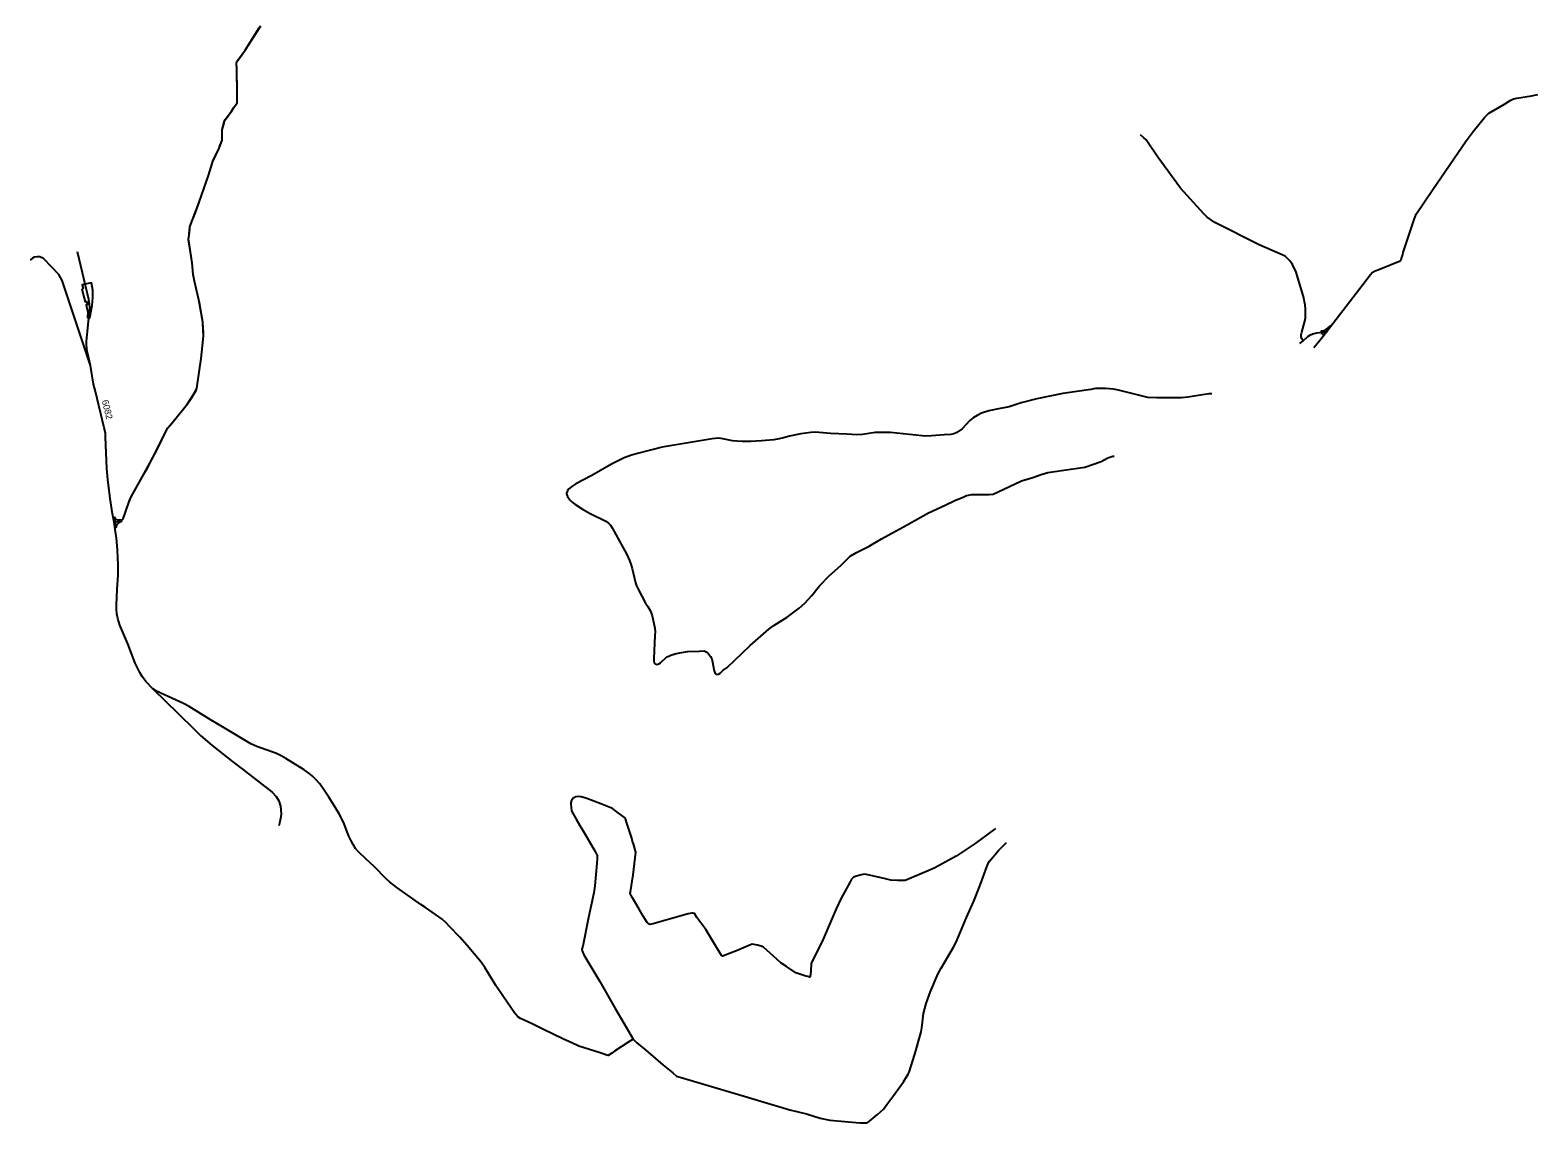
# Model space of a CAD drawing. Extents: x -444937 to -436355, y -1135022 to -1129798.
# Drawn here: x -444937 to -442668, y -1134559 to -1132915 of the extents above; entities that cross this region are included whole.
import ezdxf

# ---------------------------------------------------------------- set-up
doc = ezdxf.new("R2010")
doc.units = 0
for name, color, linetype in [('Vrstva 12', 7, 'Continuous'), ('Vrstva 29', 7, 'Continuous'), ('Vrstva 75', 7, 'Continuous'), ('Vrstva 8', 7, 'Continuous')]:
    doc.layers.add(name, color=color, linetype=linetype)

msp = doc.modelspace()

# ---------------------------------------------------------------- linework, layer by layer
at = {"layer": 'Vrstva 12'}
for points in [[(-444810.7, -1133655.8), (-444804, -1133654.8), (-444800.5, -1133653.5), (-444797.4, -1133650.5), (-444788, -1133624.4), (-444785.2, -1133617.7), (-444762.9, -1133578.2), (-444754.2, -1133561.6), (-444744.3, -1133542.3), (-444733.8, -1133521.3), (-444729.9, -1133513.9), (-444725.7, -1133508.6), (-444706.5, -1133485), (-444700.6, -1133477.9), (-444694.1, -1133467.9), (-444689.6, -1133460.8), (-444688.1, -1133458.5), (-444686.5, -1133453.9), (-444679.9, -1133409.3), (-444676.7, -1133381.1), (-444676.5, -1133375.2), (-444676.2, -1133370.9), (-444677.2, -1133354.9), (-444683.2, -1133321.2), (-444689.7, -1133293.2), (-444691.9, -1133283), (-444693.6, -1133265.4), (-444697.8, -1133236.9), (-444698.8, -1133230.7), (-444697.9, -1133223), (-444697.5, -1133216.2), (-444696.9, -1133211.3), (-444693.8, -1133203.1), (-444688.5, -1133189.8), (-444682.9, -1133174.4), (-444668.8, -1133134.2), (-444664.8, -1133121.3), (-444662.2, -1133112.9), (-444652.8, -1133093.2), (-444648, -1133081.2), (-444648, -1133075.9), (-444648.2, -1133065.2), (-444644.5, -1133052.1), (-444643.3, -1133049.9), (-444633.9, -1133036.9), (-444630.5, -1133031.8), (-444625.5, -1133024.8), (-444625.5, -1132998.6), (-444626, -1132982.6), (-444626.4, -1132973.1), (-444626.8, -1132966.9), (-444626.8, -1132965.1), (-444626.4, -1132963), (-444613.4, -1132945.4), (-444590.2, -1132908.7)], [(-443021.3, -1133382.7), (-443023.5, -1133379.8), (-443024.2, -1133376.6), (-443024.1, -1133373.8), (-443023.2, -1133370), (-443018.6, -1133353.5), (-443017.9, -1133348.3), (-443017.8, -1133342.7), (-443017.8, -1133335.4), (-443018.4, -1133328.9), (-443019.3, -1133324.4), (-443020.5, -1133318.4), (-443031.9, -1133279.7), (-443037.1, -1133267.8), (-443041.3, -1133262.4), (-443044.2, -1133259.5), (-443048.4, -1133255.7), (-443087.3, -1133238.2), (-443154.2, -1133204.7), (-443160.9, -1133200.1), (-443165.8, -1133196.8), (-443171, -1133191.6), (-443205.9, -1133153.1), (-443239.9, -1133106.7), (-443254.3, -1133085), (-443257.5, -1133080.7), (-443261.2, -1133077.3), (-443266, -1133073.1)], [(-444029.7, -1134433.4), (-444036.1, -1134437.5), (-444057.5, -1134451.4), (-444061.9, -1134454.6), (-444067.2, -1134458.1), (-444069.4, -1134457.7), (-444070.7, -1134457.1), (-444079.3, -1134454.1), (-444111.2, -1134443.9), (-444122.2, -1134438.9), (-444134.5, -1134433.4), (-444165.4, -1134418.5), (-444181.8, -1134410.6), (-444199.3, -1134402.5), (-444203.3, -1134400.1), (-444208.1, -1134393.8), (-444224.9, -1134369.7), (-444236.5, -1134352.7), (-444252.8, -1134325.6), (-444258.3, -1134317.7), (-444279.7, -1134292.7), (-444290.6, -1134279.9), (-444306, -1134263.8), (-444311.2, -1134258.5), (-444316.9, -1134253.2), (-444342.3, -1134235.7), (-444349.4, -1134230.9), (-444385.3, -1134205.4), (-444396.4, -1134196.8), (-444401.3, -1134192.1), (-444419.3, -1134173.8), (-444432.2, -1134162.1), (-444443.1, -1134151.6), (-444447.4, -1134146.5), (-444450.9, -1134140.9), (-444454.5, -1134134.2), (-444457.5, -1134127.9), (-444461.1, -1134119.1), (-444464.8, -1134109.5), (-444467.8, -1134102.9), (-444472.3, -1134094.3), (-444479, -1134082.8), (-444487.5, -1134069.6), (-444493.5, -1134060.2), (-444501.4, -1134049.5), (-444508.3, -1134041.9), (-444512.9, -1134037.4), (-444517.8, -1134033.5), (-444524.9, -1134028.5), (-444552.5, -1134011.3), (-444559.6, -1134007.3), (-444566.4, -1134004), (-444596.2, -1133993.1), (-444605.2, -1133989.1), (-444612.7, -1133984.7), (-444647.7, -1133963.4), (-444664.8, -1133953.5), (-444697.7, -1133932.8), (-444706.4, -1133928.7), (-444717.5, -1133923.6), (-444747.3, -1133909.8), (-444752.5, -1133906.4), (-444763, -1133895.2), (-444768.5, -1133888), (-444772.2, -1133882), (-444779.1, -1133867.6), (-444790.3, -1133838.9), (-444802.2, -1133810.5), (-444805.5, -1133800.4), (-444806.7, -1133793.6), (-444807.1, -1133786.4), (-444807.1, -1133780), (-444806.1, -1133757.2), (-444804.8, -1133734.8), (-444804.8, -1133720), (-444805.1, -1133709.2), (-444805.6, -1133697.4), (-444807.3, -1133679.6), (-444809.1, -1133666.7), (-444810.7, -1133655.8), (-444813.3, -1133643), (-444816.6, -1133619.9), (-444820.5, -1133591.7), (-444821.8, -1133575.2), (-444823.9, -1133527.7), (-444824, -1133521.2), (-444825.6, -1133513.8), (-444839.1, -1133459.1), (-444841.7, -1133448.2), (-444846.6, -1133419.8), (-444851.1, -1133400.2), (-444851.9, -1133394.3), (-444852.4, -1133388.4), (-444852.2, -1133384.1), (-444847.6, -1133333.3), (-444847.7, -1133327.2), (-444848.7, -1133320.5), (-444865.8, -1133249)], [(-444846.6, -1133419.8), (-444888.9, -1133292.1), (-444894.2, -1133283), (-444904.8, -1133271.9), (-444917.3, -1133259.2), (-444922.8, -1133256.5), (-444926.9, -1133256.5), (-444931, -1133257.2), (-444933.6, -1133258.7), (-444937.2, -1133261.6)], [(-443026.1, -1133386.9), (-443021.3, -1133382.7), (-443014.2, -1133376.5), (-443010.3, -1133373.8), (-443006.9, -1133372.4), (-443000.5, -1133370.7), (-442984.7, -1133368.7)], [(-443836.6, -1133533.2), (-443852.8, -1133534.1), (-443865.6, -1133534.4), (-443873.8, -1133534), (-443880.1, -1133533.4), (-443894.7, -1133530.3), (-443900.7, -1133529.4), (-443906, -1133529.7), (-443910.9, -1133530.2), (-443986.1, -1133542.8), (-444023, -1133552.5), (-444033.6, -1133555.6), (-444043.1, -1133559.1), (-444062.1, -1133568.4), (-444091.9, -1133585.3), (-444115.8, -1133598.1), (-444122.2, -1133601.8), (-444126.7, -1133605.4), (-444128.5, -1133608.4), (-444129.8, -1133612.3), (-444129.7, -1133614.7), (-444128.6, -1133617.3), (-444125, -1133622.1), (-444121.5, -1133625.8), (-444117.7, -1133628.7), (-444106.1, -1133636.3), (-444094.4, -1133642.9), (-444070.8, -1133654.2), (-444066.7, -1133657.1), (-444063.8, -1133660.4), (-444061.3, -1133664.1), (-444039.2, -1133704.5), (-444035.2, -1133713.2), (-444033, -1133718.7), (-444031.1, -1133725.3), (-444026.3, -1133747.2), (-444024.7, -1133751.6), (-444022.2, -1133756.3), (-444010.9, -1133777.6), (-444007.6, -1133782.8), (-444004.1, -1133788.4), (-444002.5, -1133792.3), (-444000.9, -1133796.8), (-443997, -1133815.4), (-443996.7, -1133820.5), (-443996.9, -1133826.1), (-443998.8, -1133860.7), (-443998.7, -1133864.5), (-443998.1, -1133867.1), (-443996.3, -1133869), (-443993.5, -1133869.7), (-443991.1, -1133869), (-443988.7, -1133867.1), (-443978.8, -1133858.3), (-443976.2, -1133857.1), (-443973, -1133855.6), (-443966.4, -1133854)], [(-444752.5, -1133906.4), (-444714.3, -1133943.6), (-444690.6, -1133967.1), (-444680.3, -1133977.2), (-444663.5, -1133991.8), (-444632.4, -1134016.4), (-444617.4, -1134027.5), (-444572.8, -1134062), (-444567, -1134068.4), (-444562.9, -1134075.2), (-444560.5, -1134083), (-444559.5, -1134094.5), (-444559.8, -1134098.9), (-444561.2, -1134106.4), (-444563.2, -1134112.5)], [(-443484.1, -1134116.4), (-443514.7, -1134139), (-443543.5, -1134158.2), (-443559.3, -1134166.8), (-443575.7, -1134176), (-443584.9, -1134179.9), (-443610.7, -1134190.8), (-443620.5, -1134194.8), (-443625.4, -1134194.8), (-443631.8, -1134194.7), (-443641.6, -1134194.3), (-443650.1, -1134192.4), (-443673.9, -1134186.9), (-443681.3, -1134185.5), (-443688.6, -1134187), (-443698.2, -1134189.6), (-443700.8, -1134193), (-443703.6, -1134197.9), (-443716.7, -1134221.2), (-443724.1, -1134237.5), (-443745.2, -1134286.4), (-443758.8, -1134313), (-443761.6, -1134319.6), (-443762.5, -1134331.1), (-443763.4, -1134339.6), (-443764.2, -1134340.2), (-443765.2, -1134340), (-443767, -1134339.5), (-443769.9, -1134338.8), (-443780.2, -1134335.3), (-443784.7, -1134333.7), (-443798.9, -1134324.4), (-443807.6, -1134318.7), (-443818.6, -1134308.9), (-443833.3, -1134295.2), (-443836.8, -1134293.6), (-443842.3, -1134292.1), (-443850.5, -1134290.6), (-443852.9, -1134291.6), (-443874.3, -1134300.5), (-443888.5, -1134306.4), (-443894.5, -1134308.7), (-443895.8, -1134308.5), (-443896.7, -1134307.7), (-443898.2, -1134305.2), (-443908.3, -1134288.4), (-443920.4, -1134268.7), (-443933.6, -1134250.4), (-443937.5, -1134244.5), (-443939.2, -1134243.8), (-443941.5, -1134243.8), (-443947, -1134245.1), (-443973.5, -1134252.5), (-443990.8, -1134257.4), (-443999.4, -1134260.1), (-444004.4, -1134261.1), (-444006.8, -1134260), (-444008.8, -1134257.8), (-444014.4, -1134248.4), (-444020.6, -1134238.2), (-444030.5, -1134221), (-444032.6, -1134217.5), (-444034, -1134214.4), (-444033.9, -1134212), (-444029.5, -1134186.5), (-444025.4, -1134152.4), (-444029.4, -1134139.8), (-444030.5, -1134136.4), (-444031.7, -1134131.3), (-444038.7, -1134109.9), (-444041.4, -1134102.2), (-444042.9, -1134100.1), (-444054.1, -1134091.3), (-444060.9, -1134086.3), (-444078.2, -1134079.3), (-444099.3, -1134071.7), (-444107.9, -1134068.9), (-444112.2, -1134068.2), (-444116, -1134069), (-444119.9, -1134071.1), (-444122.6, -1134074.3), (-444123.3, -1134077.4), (-444123.6, -1134080.2), (-444122.3, -1134089.9), (-444115.6, -1134102.4), (-444109.9, -1134112), (-444103, -1134123.5), (-444086.9, -1134151.2), (-444083.6, -1134157.3), (-444083.7, -1134161.7), (-444084.5, -1134168.8), (-444087.3, -1134203.1), (-444089, -1134213.2), (-444096.9, -1134250.7), (-444105.5, -1134293.7), (-444106.7, -1134298), (-444106.6, -1134300.6), (-444103.8, -1134306.6), (-444079.9, -1134346.7), (-444057.3, -1134386.2), (-444043.6, -1134409.3), (-444029.7, -1134433.4), (-444024.2, -1134439.2), (-444010.8, -1134450.3), (-443996.1, -1134462.6), (-443984.9, -1134472), (-443970.2, -1134484.1), (-443964.2, -1134489.1), (-443957.2, -1134491.3)], [(-443957.2, -1134491.3), (-443930.4, -1134499.2), (-443862.4, -1134519.2), (-443837.3, -1134527), (-443793.8, -1134539.9), (-443768.7, -1134546.1), (-443748, -1134552.3), (-443733.9, -1134555.2), (-443688.5, -1134559.2), (-443682.3, -1134559.4), (-443677.6, -1134559.4), (-443673.9, -1134556.8), (-443662.1, -1134546.8), (-443653.1, -1134538.9), (-443648.1, -1134531.9), (-443638.9, -1134519.8), (-443626.6, -1134503.3), (-443622.9, -1134497.7), (-443615.9, -1134486), (-443614.4, -1134483), (-443605.7, -1134456.1), (-443596.4, -1134422.7), (-443595.2, -1134416.4), (-443592.5, -1134394.8), (-443588.9, -1134380), (-443582.3, -1134361.9), (-443570.7, -1134335), (-443566.3, -1134326.5), (-443547.4, -1134295.2), (-443543.4, -1134287.6), (-443527.8, -1134250.5), (-443517.1, -1134225.7), (-443508.2, -1134204.4), (-443495.7, -1134170.2), (-443493.2, -1134165.6), (-443479.9, -1134149.8), (-443467.6, -1134137.6)]]:
    msp.add_lwpolyline(points, dxfattribs=at)
for points in [[(-442994.2, -1133371.5), (-442992.7, -1133371.6), (-442991.5, -1133372.1), (-442991, -1133372.8), (-442991.4, -1133375), (-442985.2, -1133366.6), (-442980.4, -1133360.2), (-442984.5, -1133363.9), (-442987.5, -1133366), (-442990.3, -1133367.6), (-442994.4, -1133368.5)], [(-444811, -1133647.8), (-444809.5, -1133650.1), (-444808.1, -1133651.4), (-444806, -1133652.2), (-444804.1, -1133652.3), (-444801, -1133652), (-444799.6, -1133654.6), (-444803.9, -1133656.8), (-444806.2, -1133659), (-444807.2, -1133660.7), (-444808.2, -1133663.7), (-444809.5, -1133655.4)]]:
    msp.add_lwpolyline(points, close=True, dxfattribs=at)
at = {"layer": 'Vrstva 29'}
msp.add_lwpolyline([(-444859.5, -1133304.6), (-444857.2, -1133313.2), (-444854.4, -1133324.1), (-444852.2, -1133323.5), (-444850.8, -1133328.2), (-444853, -1133328.8), (-444851.8, -1133333.5), (-444850.7, -1133337.8), (-444850.5, -1133339.9), (-444850.7, -1133348), (-444847.2, -1133348.3), (-444844.1, -1133329.9), (-444842.7, -1133317.6), (-444842.7, -1133311.8), (-444842.7, -1133306.7), (-444845.1, -1133295.5), (-444852.5, -1133297.1), (-444859, -1133298.4), (-444857.5, -1133304.1)], close=True, dxfattribs=at)
at = {"layer": 'Vrstva 75'}
for points in [[(-444810.7, -1133655.8), (-444804, -1133654.8), (-444800.5, -1133653.5), (-444797.4, -1133650.5), (-444788.5, -1133625.9), (-444786, -1133619.8), (-444785, -1133617.6), (-444763.9, -1133579.9), (-444761.6, -1133575.9), (-444752.5, -1133558.3), (-444733.8, -1133521.3), (-444729.9, -1133513.9), (-444726.6, -1133509.7), (-444708.6, -1133487.7), (-444700.6, -1133477.5), (-444694.8, -1133468.9), (-444691.4, -1133463.5), (-444688.3, -1133458.5), (-444686.5, -1133453.9), (-444679.9, -1133409.3), (-444676.7, -1133381.1), (-444676.5, -1133375.2), (-444676.8, -1133367.2), (-444677.2, -1133354.9), (-444682.3, -1133325.5), (-444689.7, -1133293.2), (-444691.9, -1133283), (-444693.6, -1133265.4), (-444697.5, -1133238.8), (-444699.1, -1133229.4), (-444698.1, -1133223.9), (-444697.1, -1133215.4), (-444696.9, -1133211.3), (-444688.7, -1133190.2), (-444682.7, -1133174), (-444668.8, -1133134.2), (-444663.2, -1133115.9), (-444662.2, -1133112.7), (-444652.8, -1133093.2), (-444651.2, -1133088.2), (-444649.3, -1133084.2), (-444648, -1133081.2), (-444648.2, -1133065.2), (-444645.9, -1133056.8), (-444644.5, -1133052.1), (-444643.6, -1133050.1), (-444634.4, -1133037.3), (-444630.5, -1133031.9), (-444627.8, -1133027.9), (-444625.5, -1133024.8), (-444625.5, -1133001.4), (-444626, -1132985.2), (-444626.4, -1132973.1), (-444626.9, -1132965.7), (-444626.4, -1132962.7), (-444613.4, -1132945.4), (-444592.4, -1132911.9)], [(-444846.6, -1133419.8), (-444888.9, -1133292.1), (-444894.2, -1133283), (-444904.8, -1133271.9), (-444917.3, -1133259.2), (-444922.8, -1133256.5), (-444926.9, -1133256.5), (-444931, -1133257.2), (-444933.6, -1133258.7), (-444937.2, -1133261.6)], [(-444810.7, -1133655.8), (-444813.3, -1133643), (-444816.6, -1133619.9), (-444820.5, -1133591.7), (-444821.8, -1133575.2), (-444823.9, -1133527.7), (-444824, -1133521.2), (-444825.6, -1133513.8), (-444839.1, -1133459.1), (-444841.7, -1133448.2), (-444846.6, -1133419.8)]]:
    msp.add_lwpolyline(points, dxfattribs=at)
at = {"layer": 'Vrstva 8'}
for points in [[(-443005, -1133392.9), (-442997.9, -1133384.1), (-442991.5, -1133376.6), (-442966.5, -1133343.6), (-442936.6, -1133304.4), (-442920, -1133283.1), (-442917.5, -1133280.2), (-442913.9, -1133278.1), (-442909, -1133276.1), (-442905, -1133274.5), (-442875.4, -1133262.5), (-442873.6, -1133260.7), (-442871.5, -1133253), (-442870.6, -1133250.1), (-442861.6, -1133223.1), (-442854.2, -1133200.1), (-442851.4, -1133192.5), (-442826, -1133155.3), (-442776, -1133082.1), (-442765.2, -1133068), (-442748.2, -1133046.7), (-442744.3, -1133042.7), (-442740.9, -1133039.9), (-442718.4, -1133026.6), (-442709.6, -1133021.4), (-442704.8, -1133018.9), (-442699.5, -1133017.8), (-442677.6, -1133014.1), (-442668, -1133012.4)], [(-443158.7, -1133462.4), (-443163, -1133462.4), (-443194.6, -1133467.5), (-443204.6, -1133468.4), (-443226.3, -1133468.5), (-443241.7, -1133468.4), (-443255.2, -1133468), (-443299.1, -1133457.3), (-443306.5, -1133455.6), (-443318.9, -1133454.6), (-443333.9, -1133454.8), (-443340.9, -1133456.1), (-443382.8, -1133462.2), (-443421.9, -1133470.3), (-443445.5, -1133476.3), (-443463.9, -1133482.2), (-443479.7, -1133485.2), (-443494.3, -1133488), (-443505.2, -1133491.7), (-443512, -1133495.1), (-443517.9, -1133498.8), (-443522.8, -1133502.5), (-443534.7, -1133515.1), (-443542.3, -1133520.7), (-443546.8, -1133522.9), (-443551.5, -1133524), (-443561.5, -1133524.5), (-443580.6, -1133525.8), (-443589, -1133526.2), (-443594.7, -1133525.8), (-443642.6, -1133520.7), (-443653, -1133520.9), (-443665.4, -1133520.9), (-443684.5, -1133523.7), (-443693.2, -1133524.3), (-443708.2, -1133523.3), (-443732.9, -1133522.3), (-443738.1, -1133521.9), (-443755.2, -1133520.4), (-443762.1, -1133520.8), (-443777.2, -1133522.6), (-443794.2, -1133526.3), (-443803.5, -1133529), (-443809.7, -1133530.3), (-443818, -1133531.6), (-443836.6, -1133533.2)], [(-443966.8, -1133853.9), (-443959.4, -1133852.2), (-443947.9, -1133850.4), (-443930.2, -1133849.6), (-443922.8, -1133849.4), (-443917.7, -1133851.9), (-443913.3, -1133858), (-443911.1, -1133861.2), (-443907.7, -1133879.2), (-443906.3, -1133883.2), (-443904.2, -1133884.8), (-443901.1, -1133884.5), (-443898.8, -1133882.7), (-443894.8, -1133879), (-443888.3, -1133874.2), (-443853.4, -1133841.2), (-443825.7, -1133816.8), (-443817.9, -1133811.2), (-443797.8, -1133798.7), (-443779.8, -1133785.1), (-443771.1, -1133777.7), (-443760.9, -1133765.9), (-443749.4, -1133751.6), (-443734.5, -1133736.6), (-443717.3, -1133721.1), (-443703, -1133707.1), (-443693.6, -1133701.4), (-443674.7, -1133691.6), (-443656, -1133681), (-443618.2, -1133660.1), (-443585, -1133641.8), (-443560.2, -1133630.3), (-443544.7, -1133622.8), (-443533.2, -1133618), (-443528, -1133615.8), (-443525.2, -1133614.9), (-443520.3, -1133614.2), (-443501.1, -1133613.9), (-443493.9, -1133614.2), (-443488, -1133613.6), (-443463, -1133601.9), (-443445.3, -1133593.6), (-443427.9, -1133588.4), (-443415.5, -1133584.1), (-443405.5, -1133580.8), (-443370.9, -1133575.9), (-443349.8, -1133573.1), (-443325.2, -1133564.6), (-443315, -1133559), (-443307.7, -1133556.4), (-443305.9, -1133556.4)]]:
    msp.add_lwpolyline(points, dxfattribs=at)

# ---------------------------------------------------------------- texts
at = {"layer": 'Vrstva 75'}
msp.add_text('6082', height=10, rotation=283.7919, dxfattribs=at).set_placement((-444829.5, -1133473))

doc.saveas('drawing.dxf')
